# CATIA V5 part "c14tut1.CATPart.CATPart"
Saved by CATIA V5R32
Part number: Part1
Bounding box of the stored display mesh (mm): x 0 to 46, y -104 to 104, z 0 to 68
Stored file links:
  D:\PROJECTS\Project 2022\CATIA V5 6R 2022\Resources\Tutorial Files\c14_catia_v5_6r2022_tut\c14tut1\c14tut1.CATPart.CATPart
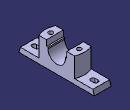
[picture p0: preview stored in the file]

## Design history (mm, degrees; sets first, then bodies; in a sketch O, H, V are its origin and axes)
Body1 (main body)
  Sketch1 on yz-plane, origin (0, 0, 0), H (0, 1, 0), V (0, 0, 1)
    axis line L1 (0, -39.4814) -> (0, 63.0107)
    point P1 (0, -39.4814)
    line L2 (0, 0) -> (104, 0)
    point P3 (104, 0)
    line L3 (104, 0) -> (100, 14)
    point P4 (100, 14)
    line L4 (100, 14) -> (54, 14)
    point P5 (54, 14)
    line L5 (54, 14) -> (54, 68)
    point P6 (54, 68)
    line L6 (54, 68) -> (28, 68)
    point P7 (28, 68)
    line L7 (28, 68) -> (28, 52)
    point P8 (28, 52)
    line L8 (28, 52) -> (24, 52)
    point P9 (24, 52)
    point P10 (0, 24)
    point P11 (-104, 0)
    point P12 (0, 0)
    line L9 (0, 0) -> (-104, 0)
    point P13 (0, 24)
    point P14 (-24, 52)
    point P15 (6.1714, 48)
    point P16 (-54, 68)
    point P17 (-28, 68)
    point P18 (-28, 52)
    line L10 (-54, 68) -> (-28, 68)
    line L11 (-28, 68) -> (-28, 52)
    line L12 (-28, 52) -> (-24, 52)
    point P19 (-54, 14)
    line L13 (-54, 14) -> (-54, 68)
    point P20 (-100, 14)
    line L14 (-100, 14) -> (-54, 14)
    line L15 (-104, 0) -> (-100, 14)
    line L16 (-24, 52) -> (-24, 48)
    line L17 (24, 52) -> (24, 48)
    arc A1 centre (0, 48) radius 24 from (-24, 48) to (24, 48) ccw
    point P23 (0, 48)
    point P24 (0, 24)
    distance P3 P11 = 208
    length L3 V = 14
    distance P17 P7 = 56
    distance P18 P17 = 16
    length L15 H = 4
    distance L6 L2 = 68
    distance L12 P23 = 4
    radius A1 = 24
    distance L13 L5 = 108
    coincidence: P1 V, L1 P10, O P12, P10 P13, A1 P24, P24 L1
    vertical: L1 V, L5 V, L7 V, L16 V, L17 V
    horizontal: L2 H, L4 H, L6 H, L8 H
    symmetry: P3 P11 L1, O P12 L1, L2 L9 L1, P10 P13 L1, P9 P14 L1, P6 P16 L1, P7 P17 L1, P8 P18 L1, L6 L10 L1, L7 L11 L1, L8 L12 L1, P5 P19 L1, L5 L13 L1, P4 P20 L1, L4 L14 L1, L3 L15 L1
    tangency: A1 L17, L16 A1
  Pad1: profile Sketch1, direction (1, 0, 0), length 46
  Sketch2 on face of Pad1, origin (0, 0, 14), H (1, 0, 0), V (0, 1, 0)
    circle A1 centre (23, 0) radius 54
    point P1 (23, 0)
    reference projected line E1 (46, 100) -> (46, 54) from edge [face of Pad1 from Sketch1.L4 | end face of Pad1]
    radius A1 = 54
    distance P1 E1 = 23
    coincidence: P1 H
  Pocket1: profile Sketch2, direction (0, 0, 1), through (limit type 3), outer side
  Sketch3 on face of Pad1 from Sketch1.L9, origin (0, 0, 0), H (1, 0, 0), V (0, -1, 0)
    point P1 (23, 39)
    line L1 (36, 52) -> (36, 26)
    line L2 (36, 26) -> (10, 26)
    line L3 (10, 26) -> (10, 52)
    line L4 (10, 52) -> (36, 52)
    reference intersected line E1 (0, 104) -> (46, 104) from face of Pad1
    reference projected line E2 (0, 104) -> (0, 0) from edge [start face of Pad1 | face of Pad1 from Sketch1.L9]
    length L3 = 26
    length L4 = 26
    distance L2 E1 = 78
    distance L3 E2 = 10
    vertical: L1 V, L3 V
    horizontal: L2 H, L4 H
    equidistance: L1 L3 P1, L2 L4 P1
  Pocket2: profile Sketch3, direction (0, 0, 1), length 10
  Sketch4 on face of Pad1, origin (24.629, 46.0353, 68), H (1, 0, 0), V (0, 1, 0)
    point P1 (-1.629, -85.0353)
    axis line L1 (11.371, -98.0353) -> (-14.629, -72.0353)
    point P2 (11.371, -98.0353)
    point P3 (-14.629, -72.0353)
    reference projected point E1 (11.371, -98.0353) from vertex [face of Pocket2 | face of Pocket2 | face of Pocket2]
    reference projected point E2 (-14.629, -72.0353) from vertex [face of Pocket2 | face of Pocket2 | face of Pocket2]
    coincidence: P2 E1, P3 E2
    midpoint: P1 L1
  Hole1: placed by Sketch4, at (23, -39, 68) direction (0, 0, -1), diameter 12, depth 100, V-bottom angle 120
  Sketch5 on face of Pad1, origin (0, 0, 14), H (1, 0, 0), V (0, 1, 0)
    construction line L1 (23, -77) -> (23, -85)
    point P2 (23, -85)
    line L2 (29, -77) -> (29, -85)
    line L3 (17, -85) -> (17, -77)
    arc A1 centre (23, -85) radius 6 from (29, -85) to (17, -85) cw
    arc A2 centre (23, -77) radius 6 from (17, -77) to (29, -77) cw
    reference projected line E1 (46, -54) -> (46, -100) from edge of Pad1
    reference projected line E2 (0, -104) -> (46, -104) from edge [face of Pad1 | face of Pad1]
    distance L1 E1 = 23
    distance P2 E2 = 19
    radius A1 = 6
    length L1 = 8
    vertical: L1 V
    tangency: A1 L2, A2 L2, A1 L3, A2 L3
    parallelism: L1 L2
  Pocket3: profile Sketch5, direction (0, 0, -1), through (limit type 3)
  Mirror1: of Pocket2, Hole1, Pocket3, about zx-plane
